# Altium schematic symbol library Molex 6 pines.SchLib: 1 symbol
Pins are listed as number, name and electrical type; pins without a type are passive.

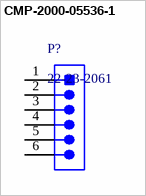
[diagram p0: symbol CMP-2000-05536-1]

## CMP-2000-05536-1
designator P?, comment 22-23-2061
Male Header, Pitch 2.54 mm, 1 x 6 Position, Height 10.67 mm, Tail Length 3.56 mm, 0 to 70 degC, RoHS, Bulk; Manufacturer: Molex; Pitch: 2.54mm; Mounting Angle: Vertical; Current Rating: 4A; Number of Positions / Contacts: 6; Voltage Rating: 250V
footprint MOLX-22-23-2061_V (THD, 6-Leads, Body 15.24x6.35mm, Pitch 2.54mm)
pins: 1, 2, 3, 4, 5, 6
